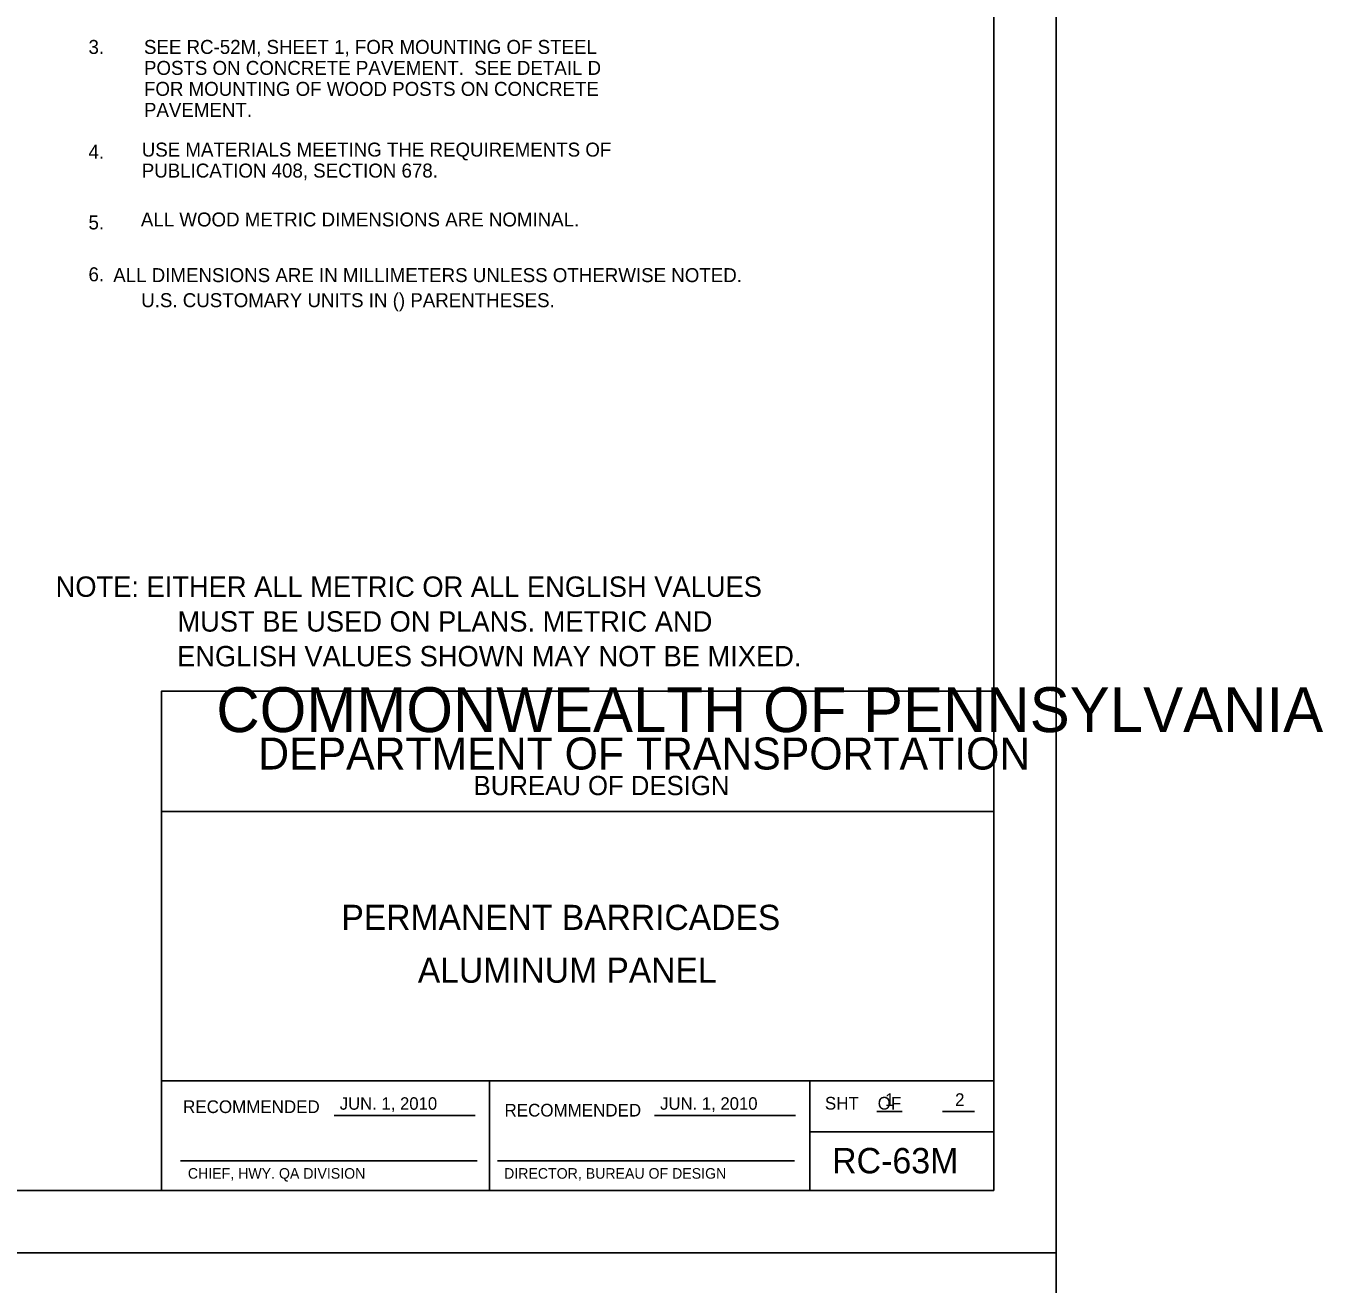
# Model space of a CAD drawing. Extents: x -4 to 901, y -468 to 720.
# Drawn here: x 589.7 to 901.4, y 118.5 to 420.9 of the extents above; entities that cross this region are included whole.
import ezdxf

# ---------------------------------------------------------------- set-up
doc = ezdxf.new("R2010")
doc.units = 0
for name, color, linetype in [('1', 7, 'Continuous'), ('2', 7, 'Continuous'), ('3', 7, 'Continuous'), ('40', 7, 'Continuous'), ('PLT-BNDY', 7, 'Continuous')]:
    doc.layers.add(name, color=color, linetype=linetype)

msp = doc.modelspace()

# ---------------------------------------------------------------- linework, layer by layer
at = {"layer": '1'}
for p, q in [((663.723, 159.016875), (697.6095, 159.016875)), ((740.721, 159.016875), (774.591, 159.016875)), ((794.1235, 160.000875), (800.2655, 160.000875)), ((809.933, 160.000875), (817.5795, 160.000875)), ((626.82025, 148.10475), (698.06975, 148.10475)), ((702.98975, 148.10475), (774.32975, 148.10475))]:
    msp.add_line(p, q, dxfattribs=at)
msp.add_lwpolyline([(822.258, 141.027875), (822.258, 705.027875), (36.258, 705.027875), (36.258, 141.027875), (822.258, 141.027875), (822.258, 167.386875), (622.258, 167.386875), (622.258, 232.064375), (822.258, 232.064375), (822.258, 261.027875), (622.258, 261.027875), (622.258, 141.027875), (701.0595, 141.027875), (701.0595, 167.386875), (701.0595, 141.027875), (778.0595, 141.027875), (778.0595, 167.386875), (778.0595, 155.070375), (822.258, 155.070375)], dxfattribs=at)
at = {"layer": 'PLT-BNDY'}
for points in [[(-3.742, 720.027875), (837.258, 720.027875), (837.258, 126.027875), (-3.742, 126.027875)], [(-3.742, 126.027875), (837.258, 126.027875), (837.258, -467.972125), (-3.742, -467.972125)]]:
    msp.add_lwpolyline(points, close=True, dxfattribs=at)

# ---------------------------------------------------------------- texts
at = {"layer": '1'}
for s, height, p in [('COMMONWEALTH OF PENNSYLVANIA', 10.7833725, (635.409, 251.171375)), ('DEPARTMENT OF TRANSPORTATION', 7.6842885, (645.47, 242.177125)), ('BUREAU OF DESIGN', 4.6220925, (697.2445, 236.014875)), ('PERMANENT BARRICADES', 6.0400005, (665.46575, 203.627875)), ('ALUMINUM PANEL', 6.0400005, (683.832, 190.935125)), ('RECOMMENDED', 3.048, (627.4215, 159.621375)), ('JUN. 1, 2010', 3, (665.061526, 160.415326)), ('JUN. 1, 2010', 3, (742.059526, 160.415326)), ('SHT    OF', 3.048, (781.6635, 160.457875)), ('1', 3.048, (796.09475, 161.319625)), ('2', 3.048, (812.9345, 161.319625)), ('RECOMMENDED', 3.048, (704.6655, 158.785125)), ('APPROVED', 0.019212, (665.281, 158.959375)), ('RC-63M', 6.096, (783.396, 145.130875)), ('CHIEF, HWY. QA DIVISION', 2.5399995, (628.569024, 143.84675)), ('DIRECTOR, BUREAU OF DESIGN', 2.5399995, (704.554841, 143.84675))]:
    msp.add_text(s, height=height, dxfattribs=at).set_placement(p)
at = {"layer": '2'}
msp.add_text('   ALL DIMENSIONS ARE IN MILLIMETERS UNLESS OTHERWISE NOTED.', height=3.361074, dxfattribs=at).set_placement((606.8835, 359.296875))
at = {"layer": '3'}
for s, height, p in [('3.  ', 3.359988, (604.68275, 414.137125)), ('SEE RC-52M, SHEET 1, FOR MOUNTING OF STEEL', 3.36, (618.01675, 414.137125)), ('SEE', 3.359988, (618.01675, 414.137125)), ('POSTS ON CONCRETE PAVEMENT.  SEE DETAIL D', 3.36, (618.01675, 409.097125)), ('FOR MOUNTING OF WOOD POSTS ON CONCRETE', 3.359988, (618.01675, 404.057125)), ('PAVEMENT.', 3.359988, (618.01675, 399.017125)), ('USE MATERIALS MEETING THE REQUIREMENTS OF', 3.359988, (617.48875, 389.461125)), ('4. ', 3.359988, (604.68275, 388.937125)), ('PUBLICATION 408, SECTION 678.', 3.359988, (617.48875, 384.421125)), ('5. ', 3.36, (604.68275, 371.965125)), ('ALL WOOD METRIC DIMENSIONS ARE NOMINAL.', 3.36, (617.271, 372.667125)), ('6. ', 3.36, (604.68275, 359.496625))]:
    msp.add_text(s, height=height, dxfattribs=at).set_placement(p)
at = {"layer": '40'}
for s, height, p in [('U.S. CUSTOMARY UNITS IN () PARENTHESES.', 3.361074, (617.352, 353.276125)), ('NOTE: EITHER ALL METRIC OR ALL ENGLISH VALUES', 4.901565, (596.78425, 283.668625)), ('MUST BE USED ON PLANS. METRIC AND', 4.901565, (626.05625, 275.316625)), ('ENGLISH VALUES SHOWN MAY NOT BE MIXED.', 4.901565, (625.97825, 266.964125))]:
    msp.add_text(s, height=height, dxfattribs=at).set_placement(p)

doc.saveas('drawing.dxf')
